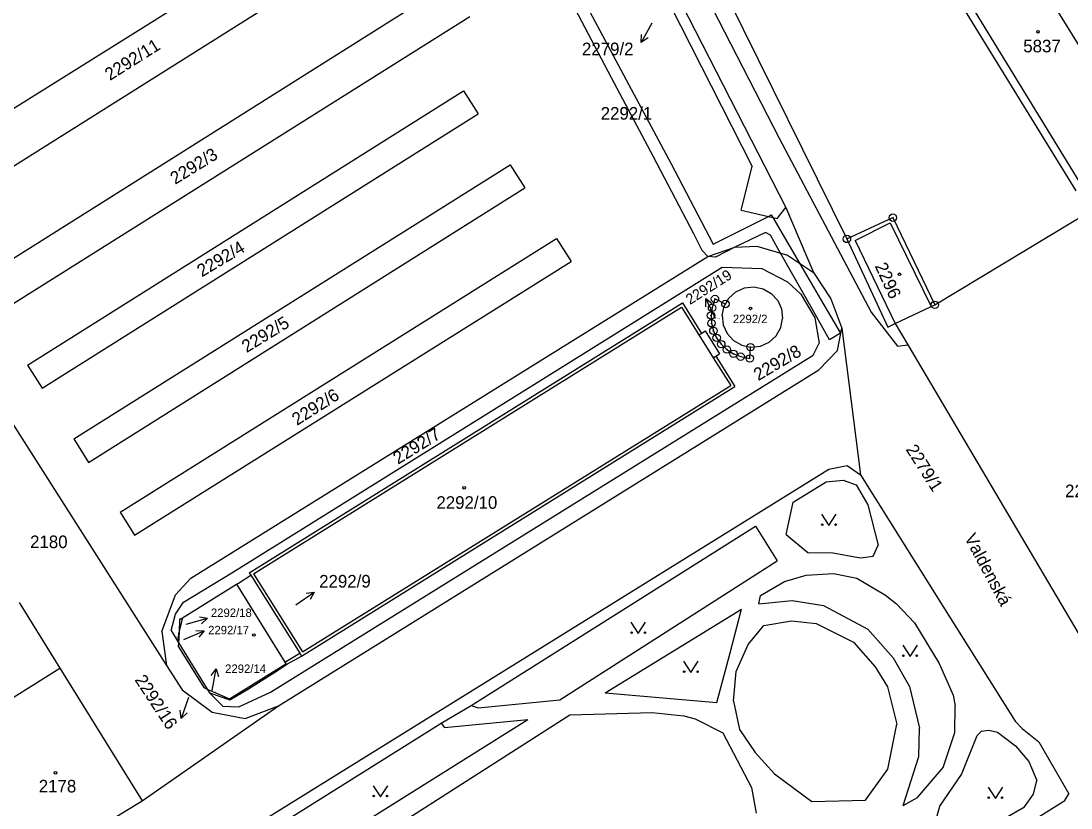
# Model space of a CAD drawing. Extents: x -735092 to -733385, y -1122435 to -1118992.
# Drawn here: x -734826.4 to -734684.8, y -1119740.7 to -1119634.5 of the extents above; entities that cross this region are included whole.
import ezdxf

# ---------------------------------------------------------------- set-up
doc = ezdxf.new("R2010")
doc.units = 0
for name, color, linetype in [('Vrstva 1', 7, 'Continuous'), ('Vrstva 15', 7, 'Continuous'), ('Vrstva 16', 7, 'Continuous'), ('Vrstva 18', 7, 'Continuous'), ('Vrstva 19', 7, 'Continuous'), ('Vrstva 25', 7, 'Continuous'), ('Vrstva 27', 7, 'Continuous'), ('Vrstva 4', 7, 'Continuous')]:
    doc.layers.add(name, color=color, linetype=linetype)

msp = doc.modelspace()

# ---------------------------------------------------------------- linework, layer by layer
at = {"layer": 'Vrstva 1'}
for points in [[(-734751.23, -1119597.69), (-734724.18, -1119650.29)], [(-734747, -1119599.28), (-734715.05, -1119663.89)], [(-734749.6, -1119608.25), (-734723.31, -1119659.67)], [(-734711.44, -1119613.13), (-734684.16, -1119657.42)], [(-734839.1, -1119653.53), (-734777.41, -1119614.97)], [(-734745.75, -1119618.79), (-734727.81, -1119654.13)], [(-734843.38, -1119664.07), (-734774.09, -1119620.45)], [(-734832.64, -1119669.72), (-734768.7, -1119629.45)], [(-734829.89, -1119674.08), (-734765.9, -1119633.89)], [(-734825.58, -1119680.93), (-734766.75, -1119643.9)], [(-734766.75, -1119643.9), (-734764.78, -1119647.03)], [(-734823.61, -1119684.04), (-734764.78, -1119647.03)], [(-734724.18, -1119650.29), (-734711.76, -1119673.76)], [(-734819.3, -1119690.88), (-734760.47, -1119653.88)], [(-734760.47, -1119653.88), (-734758.5, -1119657.01)], [(-734729.21, -1119659.63), (-734727.81, -1119654.13)], [(-734817.32, -1119694.03), (-734758.5, -1119657.01)], [(-734729.31, -1119660.02), (-734729.21, -1119659.63)], [(-734729.31, -1119660.02), (-734724.47, -1119661.12)], [(-734724.47, -1119661.12), (-734723.31, -1119659.67)], [(-734723.31, -1119659.67), (-734719.57, -1119668.42)], [(-734703.19, -1119672.77), (-734681.57, -1119659.76)], [(-734715.05, -1119663.89), (-734708.85, -1119661.02)], [(-734708.85, -1119661.02), (-734703.19, -1119672.77)], [(-734843.38, -1119664.07), (-734806.84, -1119721.42)], [(-734813.09, -1119700.75), (-734754.21, -1119663.82)], [(-734754.21, -1119663.82), (-734752.25, -1119666.92)], [(-734715.05, -1119663.89), (-734709.55, -1119675.79)], [(-734733.8, -1119666.28), (-734730.18, -1119665.02)], [(-734730.18, -1119665.02), (-734727.2, -1119664.85)], [(-734727.2, -1119664.85), (-734723.06, -1119666.07)], [(-734723.06, -1119666.07), (-734719.57, -1119668.42)], [(-734811.12, -1119703.87), (-734752.25, -1119666.92)], [(-734803.56, -1119709.64), (-734733.8, -1119666.28)], [(-734797.99, -1119708.95), (-734731.87, -1119667.69)], [(-734731.87, -1119667.69), (-734726.54, -1119667.88)], [(-734726.54, -1119667.88), (-734723.07, -1119669.66)], [(-734719.57, -1119668.42), (-734717.22, -1119671.98)], [(-734730.04, -1119671.01), (-734728.88, -1119670.49)], [(-734728.88, -1119670.49), (-734727.61, -1119670.35)], [(-734727.61, -1119670.35), (-734726.36, -1119670.6)], [(-734723.07, -1119669.66), (-734721.29, -1119671.36)], [(-734731.44, -1119672.67), (-734730.99, -1119671.88)], [(-734730.99, -1119671.88), (-734730.04, -1119671.01)], [(-734726.36, -1119670.6), (-734725.25, -1119671.23)], [(-734725.25, -1119671.23), (-734724.39, -1119672.18)], [(-734721.29, -1119671.36), (-734719.36, -1119674.55)], [(-734795.65, -1119708.93), (-734737.24, -1119672.53)], [(-734737.24, -1119672.53), (-734734.67, -1119676.63)], [(-734731.44, -1119672.67), (-734732.85, -1119671.99), (-734733.24, -1119673.18), (-734733.38, -1119674.22), (-734733.32, -1119675.27), (-734733.06, -1119676.29), (-734732.62, -1119677.24), (-734732, -1119678.09), (-734731.24, -1119678.81), (-734730.36, -1119679.38), (-734729.38, -1119679.77), (-734728.15, -1119680.01), (-734728.05, -1119678.49)], [(-734731.88, -1119674.24), (-734731.62, -1119672.98)], [(-734731.62, -1119672.98), (-734731.44, -1119672.67)], [(-734724.39, -1119672.18), (-734723.87, -1119673.34)], [(-734717.22, -1119671.98), (-734715.72, -1119675.93)], [(-734708.55, -1119675.31), (-734703.69, -1119673.02)], [(-734703.69, -1119673.02), (-734703.19, -1119672.77)], [(-734731.88, -1119674.24), (-734731.73, -1119675.5)], [(-734723.98, -1119675.86), (-734723.72, -1119674.61)], [(-734723.87, -1119673.34), (-734723.72, -1119674.61)], [(-734719.36, -1119674.55), (-734718.8, -1119677.95)], [(-734711.76, -1119673.76), (-734708.24, -1119678.35)], [(-734731.73, -1119675.5), (-734731.21, -1119676.67)], [(-734724.61, -1119676.97), (-734723.98, -1119675.86)], [(-734716.32, -1119678.92), (-734715.72, -1119675.93)], [(-734715.72, -1119675.93), (-734713.23, -1119695.7)], [(-734709.55, -1119675.79), (-734708.55, -1119675.31)], [(-734708.55, -1119675.31), (-734706.85, -1119678.19)], [(-734734.67, -1119676.63), (-734734.15, -1119676.3)], [(-734734.15, -1119676.3), (-734732.22, -1119679.37)], [(-734731.21, -1119676.67), (-734730.35, -1119677.61)], [(-734725.56, -1119677.83), (-734724.61, -1119676.97)], [(-734730.35, -1119677.61), (-734729.24, -1119678.24)], [(-734729.24, -1119678.24), (-734728.05, -1119678.49)], [(-734728.05, -1119678.49), (-734727.99, -1119678.5)], [(-734727.99, -1119678.5), (-734726.72, -1119678.36)], [(-734726.72, -1119678.36), (-734725.56, -1119677.83)], [(-734719.6, -1119679.55), (-734718.8, -1119677.95)], [(-734718.85, -1119681.55), (-734716.32, -1119678.92)], [(-734708.24, -1119678.35), (-734706.85, -1119678.19)], [(-734706.85, -1119678.19), (-734670.91, -1119738.99)], [(-734792.78, -1119725.02), (-734719.6, -1119679.55)], [(-734732.74, -1119679.7), (-734732.22, -1119679.37)], [(-734732.74, -1119679.7), (-734730.17, -1119683.81)], [(-734825.58, -1119680.93), (-734823.61, -1119684.04)], [(-734791.71, -1119726.87), (-734718.85, -1119681.55)], [(-734788.63, -1119720.16), (-734730.17, -1119683.81)], [(-734819.3, -1119690.88), (-734817.32, -1119694.03)], [(-734717.49, -1119694.96), (-734715, -1119694.46)], [(-734715, -1119694.46), (-734713.23, -1119695.7)], [(-734795.22, -1119743.21), (-734717.49, -1119694.96)], [(-734713.23, -1119695.7), (-734702.13, -1119713.43)], [(-734813.09, -1119700.75), (-734811.12, -1119703.87)], [(-734805.62, -1119711.92), (-734803.56, -1119709.64)], [(-734804.51, -1119712.91), (-734797.99, -1119708.95)], [(-734797.13, -1119710.33), (-734795.44, -1119709.27)], [(-734795.65, -1119708.93), (-734795.44, -1119709.27)], [(-734795.44, -1119709.27), (-734788.85, -1119719.76)], [(-734804.65, -1119715.01), (-734797.36, -1119710.47)], [(-734797.36, -1119710.47), (-734797.13, -1119710.33)], [(-734826.68, -1119712.93), (-734821.21, -1119721.81)], [(-734807.47, -1119716.83), (-734805.62, -1119711.92)], [(-734805.61, -1119714.51), (-734804.51, -1119712.91)], [(-734702.13, -1119713.43), (-734692.34, -1119728.95)], [(-734806.21, -1119716.73), (-734805.61, -1119714.51)], [(-734805.09, -1119716.85), (-734804.68, -1119715.15)], [(-734805.09, -1119716.85), (-734805.02, -1119715.24)], [(-734805.02, -1119715.24), (-734804.65, -1119715.01)], [(-734804.68, -1119715.15), (-734804.65, -1119715.01)], [(-734807.47, -1119716.83), (-734806.84, -1119721.42)], [(-734806.21, -1119716.73), (-734805.25, -1119718.29)], [(-734805.25, -1119718.29), (-734805.16, -1119717.14)], [(-734805.16, -1119717.14), (-734805.09, -1119716.85)], [(-734805.16, -1119718.43), (-734805.09, -1119716.85)], [(-734805.25, -1119718.29), (-734805.16, -1119718.43)], [(-734805.19, -1119718.93), (-734805.16, -1119718.43)], [(-734805.16, -1119718.43), (-734801.35, -1119724.61)], [(-734805.19, -1119718.93), (-734801.8, -1119724.41)], [(-734788.85, -1119719.76), (-734788.63, -1119720.16)], [(-734806.84, -1119721.42), (-734804.71, -1119724.73)], [(-734798.32, -1119725.93), (-734790.71, -1119721.2)], [(-734791.83, -1119722.13), (-734790.64, -1119721.32)], [(-734790.71, -1119721.2), (-734790.64, -1119721.32)], [(-734790.64, -1119721.32), (-734790.51, -1119721.23)], [(-734790.51, -1119721.23), (-734788.63, -1119720.16)], [(-734821.21, -1119721.81), (-734810.1, -1119739.69)], [(-734795.78, -1119724.57), (-734791.83, -1119722.13)], [(-734804.71, -1119724.73), (-734800.65, -1119727.71)], [(-734801.8, -1119724.41), (-734801.35, -1119724.61)], [(-734801.35, -1119724.61), (-734801.03, -1119725.12)], [(-734801.35, -1119724.61), (-734798.32, -1119725.93)], [(-734801.03, -1119725.12), (-734798.26, -1119726.05)], [(-734801.03, -1119725.12), (-734799.23, -1119726.92)], [(-734798.26, -1119726.05), (-734795.78, -1119724.57)], [(-734797.07, -1119726.99), (-734792.78, -1119725.02)], [(-734810.1, -1119739.69), (-734791.71, -1119726.87)], [(-734799.23, -1119726.92), (-734797.07, -1119726.99)], [(-734796.21, -1119728.6), (-734791.71, -1119726.87)], [(-734800.65, -1119727.71), (-734796.21, -1119728.6)], [(-734692.34, -1119728.95), (-734691.42, -1119729.95)], [(-734691.42, -1119729.95), (-734689.17, -1119731.75)], [(-734689.17, -1119731.75), (-734685.1, -1119738.73)], [(-734828.21, -1119750.77), (-734810.1, -1119739.69)], [(-734690.85, -1119742.87), (-734685.64, -1119739.63)], [(-734685.64, -1119739.63), (-734685.1, -1119738.73)]]:
    msp.add_lwpolyline(points, dxfattribs=at)
at = {"layer": 'Vrstva 25'}
for points in [[(-734741.36, -1119634.77), (-734742.786, -1119637.408)], [(-734741.871, -1119636.767), (-734742.786, -1119637.408), (-734742.751, -1119636.291)], [(-734734.099, -1119673.044), (-734734.098, -1119671.926), (-734733.204, -1119672.598)], [(-734732.76, -1119674.61), (-734734.098, -1119671.926)], [(-734718.48, -1119701.03), (-734717.48, -1119702.53), (-734716.48, -1119701.03)], [(-734789.37, -1119713.23), (-734786.895, -1119711.536)], [(-734788.003, -1119711.688), (-734786.895, -1119711.536), (-734787.438, -1119712.513)], [(-734804.17, -1119715.88), (-734801.287, -1119715.054)], [(-734802.386, -1119714.849), (-734801.287, -1119715.054), (-734802.11, -1119715.81)], [(-734744.2, -1119715.6), (-734743.2, -1119717.1), (-734742.2, -1119715.6)], [(-734804.5, -1119717.93), (-734801.731, -1119716.778)], [(-734802.846, -1119716.7), (-734801.731, -1119716.778), (-734802.462, -1119717.624)], [(-734707.53, -1119718.71), (-734706.53, -1119720.21), (-734705.53, -1119718.71)], [(-734737.1, -1119720.87), (-734736.1, -1119722.37), (-734735.1, -1119720.87)], [(-734800.777, -1119722.764), (-734800.109, -1119721.868), (-734799.794, -1119722.941)], [(-734800.64, -1119724.82), (-734800.109, -1119721.868)], [(-734803.85, -1119725.76), (-734804.861, -1119728.584)], [(-734804.053, -1119727.811), (-734804.861, -1119728.584), (-734804.994, -1119727.474)], [(-734778.97, -1119737.65), (-734777.97, -1119739.15), (-734776.97, -1119737.65)], [(-734696.02, -1119737.87), (-734695.02, -1119739.37), (-734694.02, -1119737.87)]]:
    msp.add_lwpolyline(points, dxfattribs=at)
for centre, radius in [((-734689.28, -1119635.95), 0.175), ((-734708.85, -1119661.02), 0.5), ((-734708.85, -1119661.02), 0.032), ((-734715.05, -1119663.89), 0.5), ((-734715.05, -1119663.89), 0.032), ((-734707.95, -1119668.66), 0.174), ((-734732.85, -1119671.99), 0.5), ((-734733.24, -1119673.18), 0.5), ((-734733.24, -1119673.18), 0.032), ((-734732.85, -1119671.99), 0.032), ((-734731.44, -1119672.67), 0.5), ((-734731.44, -1119672.67), 0.032), ((-734728.06, -1119673.26), 0.175), ((-734703.19, -1119672.77), 0.5), ((-734703.19, -1119672.77), 0.032), ((-734733.38, -1119674.22), 0.5), ((-734733.38, -1119674.22), 0.032), ((-734733.32, -1119675.27), 0.5), ((-734733.06, -1119676.29), 0.5), ((-734733.32, -1119675.27), 0.032), ((-734732.62, -1119677.24), 0.5), ((-734733.06, -1119676.29), 0.032), ((-734732.62, -1119677.24), 0.032), ((-734732, -1119678.09), 0.5), ((-734732, -1119678.09), 0.032), ((-734731.24, -1119678.81), 0.5), ((-734731.24, -1119678.81), 0.032), ((-734730.36, -1119679.38), 0.5), ((-734728.05, -1119678.49), 0.5), ((-734728.05, -1119678.49), 0.032), ((-734730.36, -1119679.38), 0.032), ((-734729.38, -1119679.77), 0.5), ((-734729.38, -1119679.77), 0.032), ((-734728.15, -1119680.01), 0.5), ((-734728.15, -1119680.01), 0.032), ((-734766.68, -1119697.47), 0.175), ((-734718.38, -1119702.43), 0.1), ((-734716.58, -1119702.43), 0.1), ((-734795.04, -1119717.32), 0.175), ((-734744.1, -1119717), 0.1), ((-734742.3, -1119717), 0.1), ((-734707.43, -1119720.11), 0.1), ((-734705.63, -1119720.11), 0.1), ((-734737, -1119722.27), 0.1), ((-734735.2, -1119722.27), 0.1), ((-734821.79, -1119735.92), 0.175), ((-734778.87, -1119739.05), 0.1), ((-734777.07, -1119739.05), 0.1), ((-734695.92, -1119739.27), 0.1), ((-734694.12, -1119739.27), 0.1)]:
    msp.add_circle(centre, radius, dxfattribs=at)
at = {"layer": 'Vrstva 27'}
for points in [[(-734746.8, -1119642.16), (-734753.02, -1119630.31)], [(-734750.11, -1119632.49), (-734744.48, -1119643.08)], [(-734741.16, -1119652.83), (-734746.8, -1119642.16)], [(-734744.48, -1119643.08), (-734738.81, -1119653.67)], [(-734735.7, -1119663.21), (-734741.16, -1119652.83)], [(-734738.81, -1119653.67), (-734733.09, -1119664.59)], [(-734733.09, -1119664.59), (-734725.65, -1119660.85)], [(-734725.65, -1119660.85), (-734725.25, -1119660.65)], [(-734725.25, -1119660.65), (-734725.06, -1119660.99)], [(-734725.06, -1119660.99), (-734721.47, -1119667.14)], [(-734734.56, -1119665.46), (-734735.7, -1119663.21)], [(-734726.05, -1119663.03), (-734730.18, -1119665.02)], [(-734725.36, -1119663.39), (-734726.05, -1119663.03)], [(-734724.38, -1119665.16), (-734725.36, -1119663.39)], [(-734733.8, -1119666.28), (-734734.56, -1119665.46)], [(-734730.18, -1119665.02), (-734732.79, -1119666.35)], [(-734724.02, -1119665.79), (-734724.38, -1119665.16)], [(-734719.73, -1119673.33), (-734724.02, -1119665.79)], [(-734732.79, -1119666.35), (-734733.8, -1119666.28)], [(-734721.47, -1119667.14), (-734718.62, -1119672.03)], [(-734717.42, -1119677.51), (-734719.73, -1119673.33)], [(-734718.62, -1119672.03), (-734715.92, -1119676.62)], [(-734715.92, -1119676.62), (-734717.42, -1119677.51)]]:
    msp.add_lwpolyline(points, dxfattribs=at)
at = {"layer": 'Vrstva 4'}
for points in [[(-734701.04, -1119609.9), (-734674.67, -1119652.46)], [(-734708.92, -1119615.03), (-734683.3, -1119656.89)], [(-734713.95, -1119664.09), (-734709.23, -1119661.71)], [(-734709.23, -1119661.71), (-734703.69, -1119673.02)], [(-734713.95, -1119664.09), (-734708.55, -1119675.31)], [(-734795.1, -1119709.06), (-734737.37, -1119673.08)], [(-734737.37, -1119673.08), (-734735.01, -1119676.84)], [(-734735.01, -1119676.84), (-734734.67, -1119676.63)], [(-734735.01, -1119676.84), (-734733.08, -1119679.92)], [(-734733.08, -1119679.92), (-734732.74, -1119679.7)], [(-734733.08, -1119679.92), (-734730.72, -1119683.68)], [(-734788.5, -1119719.61), (-734730.72, -1119683.68)], [(-734722.31, -1119699.41), (-734717.85, -1119696.66)], [(-734717.85, -1119696.66), (-734715.55, -1119696.43)], [(-734715.55, -1119696.43), (-734713.8, -1119697.05)], [(-734713.8, -1119697.05), (-734712.22, -1119699.77)], [(-734723.26, -1119703.78), (-734722.31, -1119699.41)], [(-734712.22, -1119699.77), (-734710.85, -1119705.22)], [(-734765.75, -1119726.83), (-734727.37, -1119702.64)], [(-734727.37, -1119702.64), (-734724.44, -1119707.3)], [(-734723.26, -1119703.78), (-734720.31, -1119706.21)], [(-734711.51, -1119706.69), (-734710.85, -1119705.22)], [(-734753.76, -1119726.05), (-734724.44, -1119707.3)], [(-734720.31, -1119706.21), (-734716.93, -1119706.24)], [(-734716.93, -1119706.24), (-734713.2, -1119706.91)], [(-734713.2, -1119706.91), (-734711.51, -1119706.69)], [(-734795.1, -1119709.06), (-734788.5, -1119719.61)], [(-734726.73, -1119712), (-734723.48, -1119710.1)], [(-734723.48, -1119710.1), (-734720.55, -1119709.23)], [(-734720.55, -1119709.23), (-734716.87, -1119709.03)], [(-734716.87, -1119709.03), (-734713.7, -1119709.64)], [(-734713.7, -1119709.64), (-734709.83, -1119711.94)], [(-734797.36, -1119710.47), (-734790.84, -1119721)], [(-734726.91, -1119713.13), (-734726.73, -1119712)], [(-734726.91, -1119713.13), (-734722.44, -1119712.66)], [(-734722.44, -1119712.66), (-734718.23, -1119713.33)], [(-734709.83, -1119711.94), (-734708.36, -1119713.13)], [(-734747.68, -1119725.11), (-734729.25, -1119713.84)], [(-734730.8, -1119719.74), (-734729.25, -1119713.84)], [(-734718.23, -1119713.33), (-734712.24, -1119716.53)], [(-734708.36, -1119713.13), (-734705.93, -1119715.66)], [(-734726.24, -1119716.05), (-734722.52, -1119715.42)], [(-734722.52, -1119715.42), (-734719.21, -1119715.78)], [(-734719.21, -1119715.78), (-734714.18, -1119718.27)], [(-734705.93, -1119715.66), (-734702.63, -1119721.17)], [(-734728.38, -1119718.59), (-734726.24, -1119716.05)], [(-734712.24, -1119716.53), (-734708.82, -1119720.41)], [(-734729.98, -1119722.25), (-734728.38, -1119718.59)], [(-734714.18, -1119718.27), (-734711.26, -1119721.62)], [(-734790.84, -1119721), (-734788.85, -1119719.76)], [(-734732.59, -1119726.42), (-734730.8, -1119719.74)], [(-734790.84, -1119721), (-734790.71, -1119721.2)], [(-734708.82, -1119720.41), (-734706.63, -1119724.27)], [(-734702.63, -1119721.17), (-734700.74, -1119725.45)], [(-734832.83, -1119729.08), (-734821.21, -1119721.81)], [(-734730.37, -1119726.23), (-734729.98, -1119722.25)], [(-734711.26, -1119721.62), (-734709.58, -1119724.3)], [(-734709.58, -1119724.3), (-734708.34, -1119729.35)], [(-734706.63, -1119724.27), (-734705.26, -1119729.9)], [(-734747.68, -1119725.11), (-734732.59, -1119726.42)], [(-734700.74, -1119725.45), (-734700.46, -1119726.94)], [(-734769.76, -1119729.22), (-734765.75, -1119726.83)], [(-734765.75, -1119726.83), (-734764.78, -1119727.13)], [(-734764.78, -1119727.13), (-734753.76, -1119726.05)], [(-734730.37, -1119726.23), (-734729.54, -1119730.08)], [(-734700.48, -1119730.48), (-734700.46, -1119726.94)], [(-734789.86, -1119752.07), (-734752.43, -1119728.07)], [(-734752.43, -1119728.07), (-734741.34, -1119727.78)], [(-734741.34, -1119727.78), (-734737.07, -1119728.21)], [(-734737.07, -1119728.21), (-734735.54, -1119728.65)], [(-734794.35, -1119744.64), (-734769.76, -1119729.22)], [(-734791.36, -1119749.59), (-734758.07, -1119728.7)], [(-734769.76, -1119729.22), (-734769.34, -1119729.79)], [(-734769.34, -1119729.79), (-734758.07, -1119728.7)], [(-734735.54, -1119728.65), (-734731.78, -1119730.51)], [(-734709.53, -1119735.42), (-734708.34, -1119729.35)], [(-734705.34, -1119733.69), (-734705.26, -1119729.9)], [(-734731.78, -1119730.51), (-734727.94, -1119737.88)], [(-734729.54, -1119730.08), (-734727.43, -1119733.16)], [(-734702.06, -1119735.19), (-734700.48, -1119730.48)], [(-734699.6, -1119736.12), (-734697.47, -1119730.86)], [(-734697.47, -1119730.86), (-734696.92, -1119730.3)], [(-734696.92, -1119730.3), (-734695.9, -1119730.16)], [(-734695.9, -1119730.16), (-734694.73, -1119730.44)], [(-734694.73, -1119730.44), (-734692.31, -1119732.26)], [(-734692.31, -1119732.26), (-734690.52, -1119734.39)], [(-734727.43, -1119733.16), (-734724.82, -1119736.03)], [(-734707.46, -1119740.3), (-734705.34, -1119733.69)], [(-734712.55, -1119739.59), (-734709.53, -1119735.42)], [(-734705.55, -1119739.23), (-734702.06, -1119735.19)], [(-734690.52, -1119734.39), (-734689.42, -1119736.95)], [(-734724.82, -1119736.03), (-734719.78, -1119739.8)], [(-734702.53, -1119740.42), (-734699.6, -1119736.12)], [(-734689.87, -1119738.78), (-734689.42, -1119736.95)], [(-734727.94, -1119737.88), (-734727.3, -1119741.37)], [(-734719.78, -1119739.8), (-734712.55, -1119739.59)], [(-734707.46, -1119740.3), (-734705.55, -1119739.23)], [(-734691.11, -1119740.52), (-734689.87, -1119738.78)], [(-734702.86, -1119741.72), (-734702.53, -1119740.42)], [(-734698.33, -1119744.67), (-734691.11, -1119740.52)]]:
    msp.add_lwpolyline(points, dxfattribs=at)

# ---------------------------------------------------------------- texts
at = {"layer": 'Vrstva 15'}
msp.add_text('Valdenská', height=1.7, rotation=298.10237, dxfattribs=at).set_placement((-734699.26, -1119704.192))
at = {"layer": 'Vrstva 16'}
for s, height, p in [('2279/2', 1.7, (-734750.787, -1119639.11)), ('2292/9', 1.7, (-734786.23, -1119710.92)), ('2292/18', 1.14, (-734800.83, -1119714.89)), ('2292/17', 1.14, (-734801.2, -1119717.229)), ('2292/14', 1.14, (-734798.91, -1119722.439))]:
    msp.add_text(s, height=height, dxfattribs=at).set_placement(p)
for s, height, rotation, p in [('2292/19', 1.42, 32.40026, (-734736.213, -1119672.808)), ('2292/16', 1.7, 303.40241, (-734811.174, -1119723.373))]:
    msp.add_text(s, height=height, rotation=rotation, dxfattribs=at).set_placement(p)
at = {"layer": 'Vrstva 18'}
for s, height, rotation, p in [('2292/11', 1.7, 32.20026, (-734814.458, -1119642.595)), ('2292/3', 1.7, 31.70025, (-734805.655, -1119656.605)), ('2292/4', 1.7, 30.80024, (-734802.061, -1119669.086)), ('2292/5', 1.7, 31.50025, (-734796.014, -1119679.295)), ('2292/8', 1.7, 30.70024, (-734727.003, -1119683.082)), ('2292/6', 1.7, 32.40026, (-734789.219, -1119689.124)), ('2292/7', 1.7, 31.70025, (-734775.595, -1119694.355)), ('2279/1', 1.7, 302.50241, (-734707.174, -1119692.281)), ('2292/17', 0.1, 86.60069, (-734805.377, -1119717.959)), ('2292/14', 0.1, 336.70268, (-734800.408, -1119724.996))]:
    msp.add_text(s, height=height, rotation=rotation, dxfattribs=at).set_placement(p)
for s, height, p in [('2292/1', 1.7, (-734748.26, -1119647.8)), ('2292/19', 0.1, (-734732.671, -1119674.7)), ('2297/1', 1.7, (-734685.63, -1119698.73)), ('2180', 1.7, (-734825.22, -1119705.6))]:
    msp.add_text(s, height=height, dxfattribs=at).set_placement(p)
at = {"layer": 'Vrstva 19'}
for s, height, p in [('5837', 1.7, (-734691.27, -1119638.72)), ('2292/2', 1.14, (-734730.43, -1119675.25)), ('2292/10', 1.7, (-734770.42, -1119700.3)), ('2292/9', 0.1, (-734792.76, -1119715.49)), ('2178', 1.7, (-734824.05, -1119738.56))]:
    msp.add_text(s, height=height, dxfattribs=at).set_placement(p)
for s, height, rotation, p in [('2296', 1.7, 294.60234, (-734711.325, -1119667.538)), ('2292/18', 0.1, 78.00062, (-734805.044, -1119715.533)), ('2292/16', 0.1, 301.8024, (-734802.475, -1119722.764))]:
    msp.add_text(s, height=height, rotation=rotation, dxfattribs=at).set_placement(p)

doc.saveas('drawing.dxf')
